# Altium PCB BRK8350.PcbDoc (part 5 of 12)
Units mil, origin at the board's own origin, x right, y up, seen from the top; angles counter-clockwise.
Board outline 9448.82 x 5905.51 mil, 8 copper layers (L1-TOP, L2-GND, L3-SIG, L4-GND, L5-PWR, L6-PWR, L7-GND, L8-BOT), stack 57.69 mil thick; 288 components, 543 nets, 1891 pads, 2032 vias.
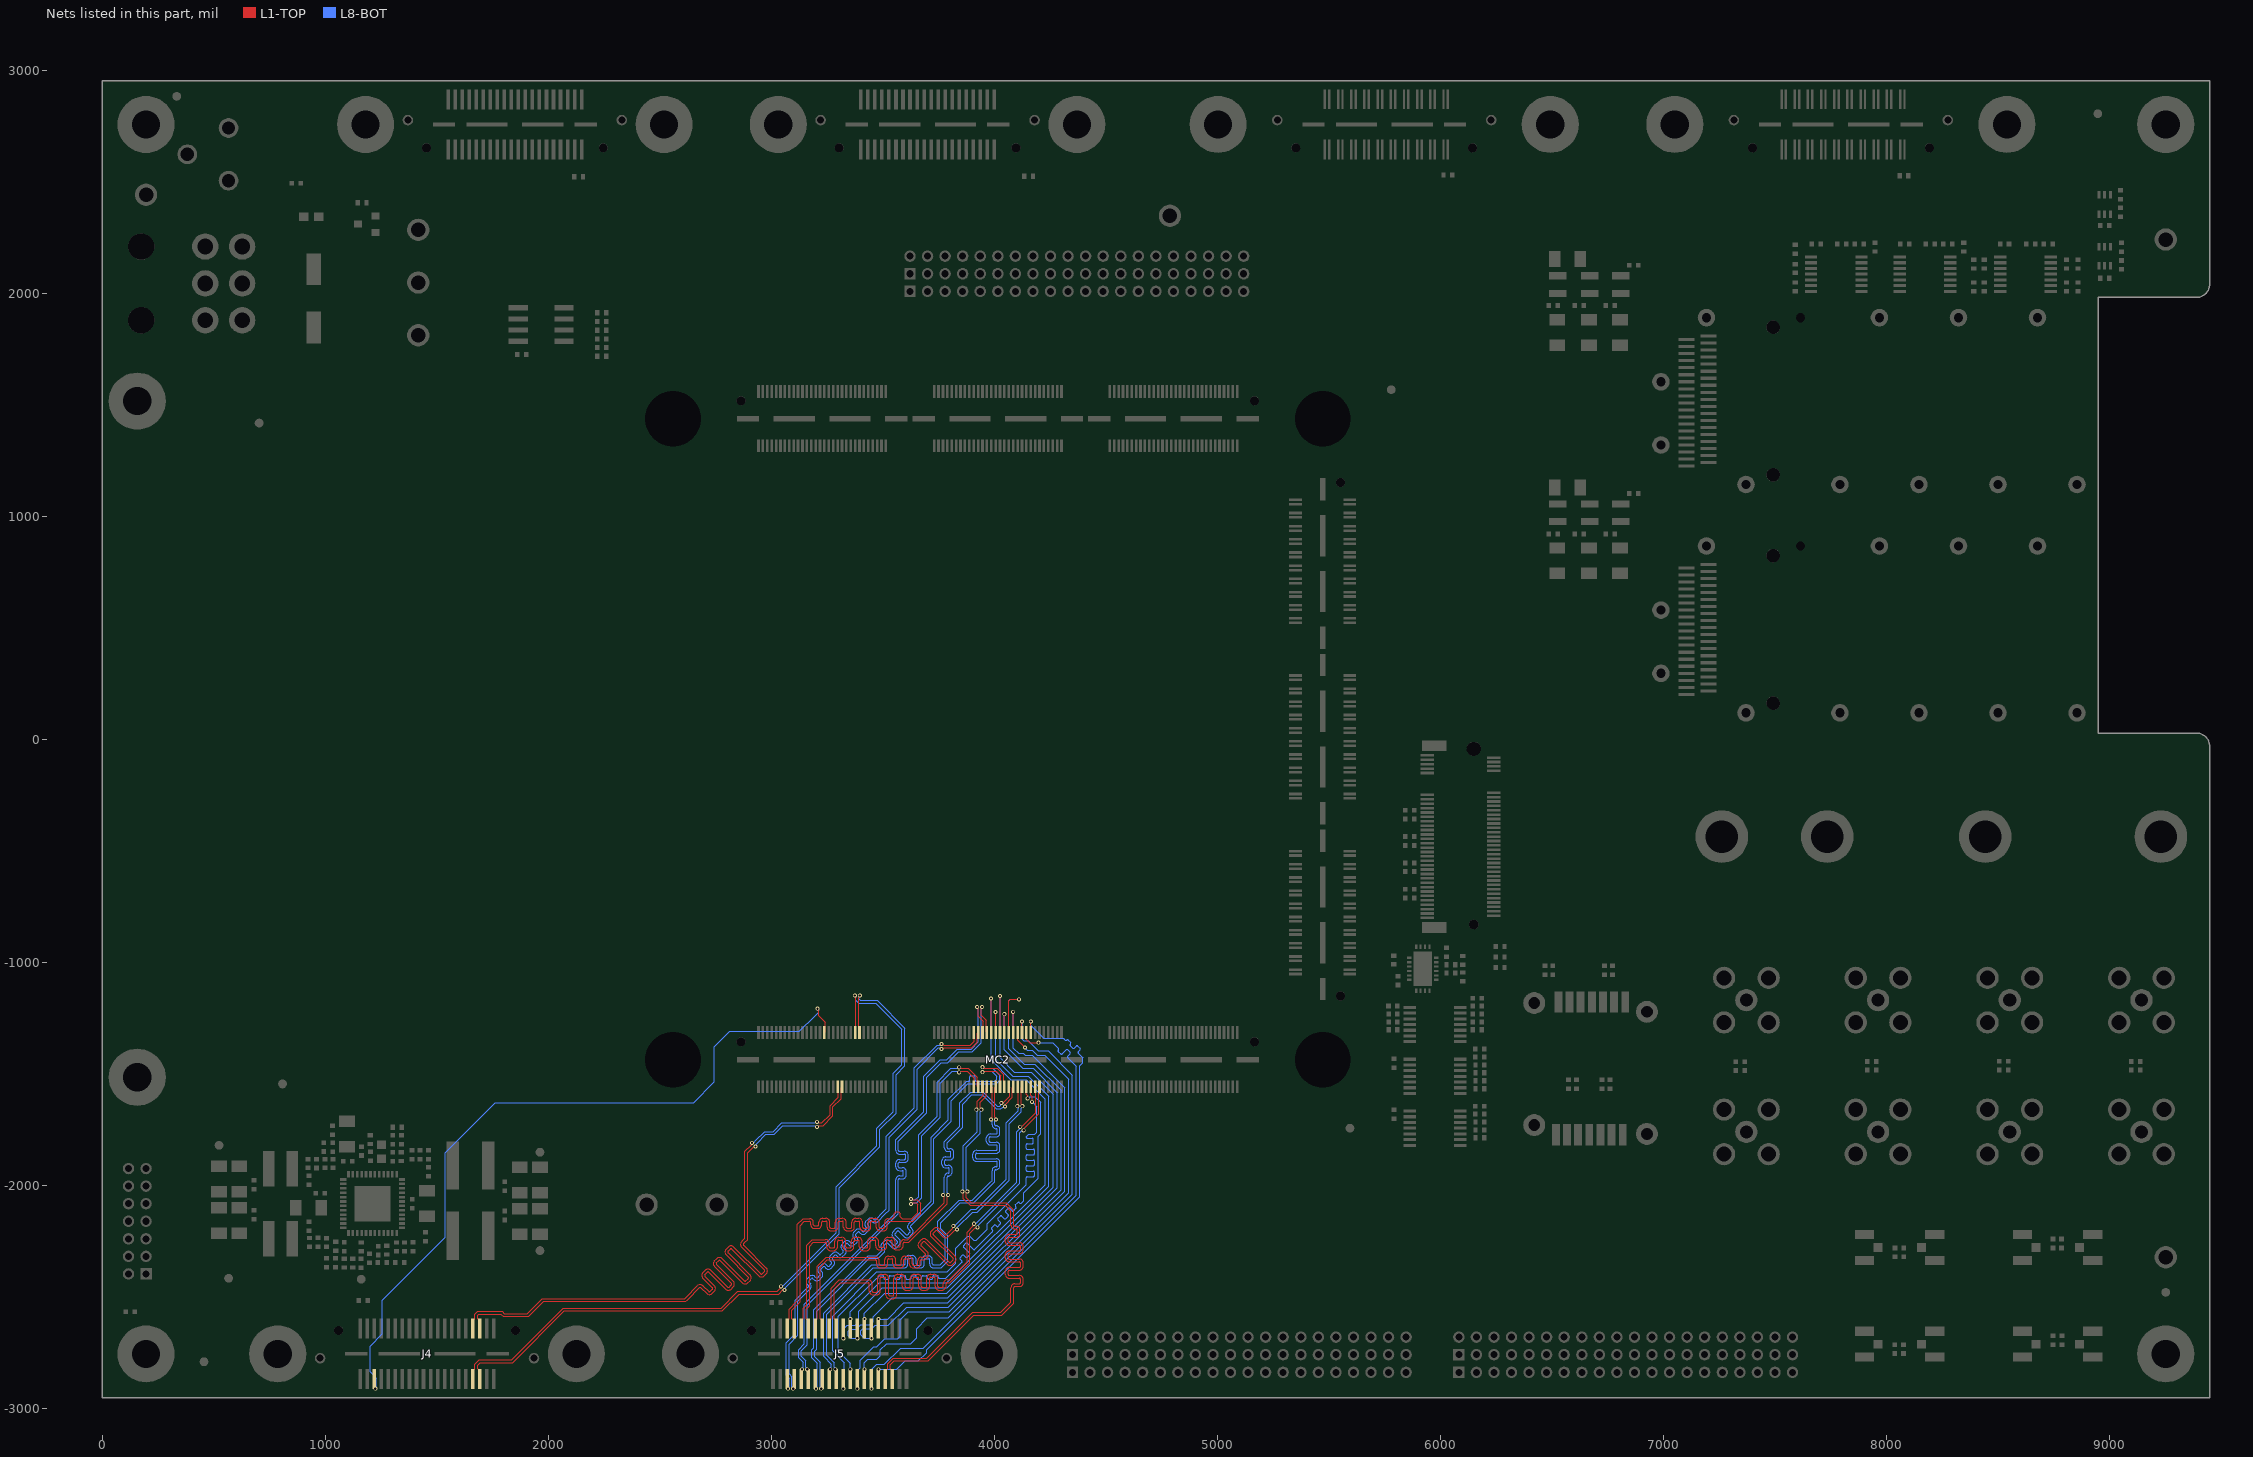
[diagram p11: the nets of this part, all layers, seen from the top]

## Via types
v1: diameter 18, hole 10, L1-TOP to L8-BOT, tented both sides, 2032 vias

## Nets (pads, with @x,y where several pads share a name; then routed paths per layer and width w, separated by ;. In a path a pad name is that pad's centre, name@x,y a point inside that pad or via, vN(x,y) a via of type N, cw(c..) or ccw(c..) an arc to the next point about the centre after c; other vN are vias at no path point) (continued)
PORTA_P2C_CLKN: J5.35 MC2.86 | length 2319.9
  L1-TOP w4.2: J5.35@3543.34,-2868.71 3543.34,-2831.96 3537.44,-2826.06 3536.35,-2826.06 3533.89,-2823.6 3533.89,-2804.85 3551.34,-2787.4 3702.86,-2787.4 3907.58,-2582.68 4033.57,-2582.68 4087.4,-2528.84 4087.4,-2503.94 4087.4,-2458.74 cw(c4092.24,-2458.74) 4092.24,-2453.9 4112.69,-2453.9 ccw(c4112.69,-2436.46) 4130.13,-2436.46 4130.13,-2421.94 ccw(c4112.69,-2421.94) 4112.69,-2404.5 4067.24,-2404.5 cw(c4067.24,-2399.66) 4062.4,-2399.66 4062.4,-2385.14 cw(c4067.24,-2385.14) 4067.24,-2380.3 4112.69,-2380.3 ccw(c4112.69,-2362.86) 4130.13,-2362.86 4130.13,-2348.34 ccw(c4112.69,-2348.34) 4112.69,-2330.9 4067.24,-2330.9 cw(c4067.24,-2326.06) 4062.4,-2326.06 4062.4,-2311.54 cw(c4067.24,-2311.54) 4067.24,-2306.7 4112.69,-2306.7 ccw(c4112.69,-2289.26) 4130.13,-2289.26 4130.13,-2274.74 ccw(c4112.69,-2274.74) 4112.69,-2257.3 4067.24,-2257.3 cw(c4067.24,-2252.46) 4062.4,-2252.46 4062.4,-2237.94 cw(c4067.24,-2237.94) 4067.24,-2233.1 4097.43,-2233.1 ccw(c4097.43,-2215.66) 4114.87,-2215.66 4114.87,-2201.14 ccw(c4097.43,-2201.14) 4097.43,-2183.7 4092.24,-2183.7 cw(c4092.24,-2178.86) 4087.4,-2178.86 4087.4,-2125.98 4087.4,-2111.03 4054.33,-2077.95 3896.85,-2077.95 3874.02,-2055.12 3874.02,-2030.02 3876.48,-2027.56 v1(3878.97,-2027.56) ; v1(3941.96,-1661.42) 3941.96,-1658.49 3937.01,-1653.54 3937.01,-1628.06 3963.01,-1602.05 3963.01,-1562.19 MC2.86@3966.55,-1558.65
  L8-BOT w4.2: v1(3878.97,-2027.56) 3878.97,-2023.82 3874.02,-2018.87 3874.02,-1828.84 3937.01,-1765.85 3937.01,-1670.1 3941.96,-1665.15 v1(3941.96,-1661.42)
PORTA_P2C_CLKP: J5.33 MC2.84 | length 2319.9
  L1-TOP w4.2: J5.33@3511.84,-2868.71 3511.84,-2831.96 3517.74,-2826.06 3518.83,-2826.06 3521.29,-2823.6 3521.29,-2799.63 3546.12,-2774.8 3697.64,-2774.8 3902.36,-2570.08 4028.35,-2570.08 4074.8,-2523.62 4074.8,-2503.94 4074.8,-2458.74 cw(c4092.24,-2458.74) 4092.24,-2441.3 4112.69,-2441.3 ccw(c4112.69,-2436.46) 4117.53,-2436.46 4117.53,-2421.94 ccw(c4112.69,-2421.94) 4112.69,-2417.1 4067.24,-2417.1 cw(c4067.24,-2399.66) 4049.8,-2399.66 4049.8,-2385.14 cw(c4067.24,-2385.14) 4067.24,-2367.7 4112.69,-2367.7 ccw(c4112.69,-2362.86) 4117.53,-2362.86 4117.53,-2348.34 ccw(c4112.69,-2348.34) 4112.69,-2343.5 4067.24,-2343.5 cw(c4067.24,-2326.06) 4049.8,-2326.06 4049.8,-2311.54 cw(c4067.24,-2311.54) 4067.24,-2294.1 4112.69,-2294.1 ccw(c4112.69,-2289.26) 4117.53,-2289.26 4117.53,-2274.74 ccw(c4112.69,-2274.74) 4112.69,-2269.9 4067.24,-2269.9 cw(c4067.24,-2252.46) 4049.8,-2252.46 4049.8,-2237.94 cw(c4067.24,-2237.94) 4067.24,-2220.5 4097.43,-2220.5 ccw(c4097.43,-2215.66) 4102.27,-2215.66 4102.27,-2201.14 ccw(c4097.43,-2201.14) 4097.43,-2196.3 4092.24,-2196.3 cw(c4092.24,-2178.86) 4074.8,-2178.86 4074.8,-2125.98 4074.8,-2116.24 4049.11,-2090.55 3891.63,-2090.55 3861.42,-2060.34 3861.42,-2030.02 3858.93,-2030.02 v1(3856.47,-2027.56) ; v1(3919.46,-1661.42) 3919.46,-1658.49 3924.41,-1653.54 3924.41,-1622.84 3950.41,-1596.84 3950.41,-1562.19 MC2.84@3946.87,-1558.65
  L8-BOT w4.2: v1(3856.47,-2027.56) 3856.47,-2023.82 3861.42,-2018.87 3861.42,-1823.62 3924.41,-1760.63 3924.41,-1670.1 3919.46,-1665.15 v1(3919.46,-1661.42)
PORTA_S0_D0P: J5.5 MC2.79 | length 2272.5
  L1-TOP w4.2: v1(3763.8,-1366.81) 3767.53,-1366.81 3772.48,-1371.76 3892.96,-1371.76 3911.04,-1353.68 3911.04,-1318.88 MC2.79@3907.5,-1315.34
  L8-BOT w4.2: v1(3075.05,-2912.07) 3075.05,-2908.34 3080.29,-2903.1 3080.29,-2864.61 3066.93,-2851.25 3066.93,-2706.59 3106.82,-2666.7 3106.82,-2515.17 3159.88,-2462.11 3165.82,-2456.17 ccw(c3162.4,-2452.75) 3165.8,-2449.3 ; 3165.79,-2449.29 3161.08,-2444.59 cw(c3173.41,-2432.25) 3161.08,-2419.92 3171.35,-2409.65 cw(c3183.68,-2421.99) 3196.01,-2409.65 3200.75,-2414.39 ccw(c3204.17,-2410.97) 3207.6,-2414.39 3217.86,-2404.13 ccw(c3214.44,-2400.7) 3217.86,-2397.28 3213.12,-2392.54 cw(c3225.46,-2380.21) 3213.12,-2367.88 3223.39,-2357.61 cw(c3235.72,-2369.94) 3248.05,-2357.61 3252.79,-2362.35 ccw(c3256.22,-2358.93) 3259.64,-2362.35 3269.91,-2352.08 ccw(c3266.48,-2348.66) 3269.91,-2345.24 3265.17,-2340.5 cw(c3277.5,-2328.17) 3265.17,-2315.84 3275.43,-2305.57 cw(c3287.77,-2317.9) 3300.1,-2305.57 3304.84,-2310.31 ccw(c3308.26,-2306.88) 3311.68,-2310.31 3321.95,-2300.04 ccw(c3318.53,-2296.62) 3321.95,-2293.19 3317.21,-2288.46 cw(c3329.54,-2276.12) 3317.21,-2263.79 3327.48,-2253.53 cw(c3339.81,-2265.86) 3352.14,-2253.53 3356.88,-2258.26 ccw(c3360.3,-2254.84) 3363.72,-2258.26 3373.99,-2248 ccw(c3370.57,-2244.57) 3373.99,-2241.15 3369.25,-2236.41 cw(c3381.58,-2224.08) 3369.25,-2211.75 3379.52,-2201.48 cw(c3391.85,-2213.81) 3404.18,-2201.48 3408.92,-2206.22 ccw(c3412.34,-2202.8) 3415.77,-2206.22 3426.03,-2195.95 ccw(c3422.61,-2192.53) 3426.03,-2189.11 3423.92,-2186.99 cw(c3436.25,-2174.66) 3423.92,-2162.33 3434.18,-2152.06 cw(c3446.52,-2164.39) 3458.85,-2152.06 3460.97,-2154.18 ccw(c3464.39,-2150.76) 3467.81,-2154.18 3502.06,-2119.93 3515.75,-2106.24 3515.75,-1779.53 3641.73,-1653.54 3641.73,-1474.1 3744.43,-1371.4 3755.47,-1371.4 3760.06,-1366.81 v1(3763.8,-1366.81)
PORTA_S1_D1P: J5.6 MC2.80 | length 2320.2
  L1-TOP w4.2: J5.6@3070.84,-2643.11 3070.84,-2606.36 3076.74,-2600.46 3077.83,-2600.46 3080.29,-2598 3080.29,-2555.26 3117.32,-2518.23 3117.32,-2175.88 3143.6,-2149.61 3148.82,-2149.61 3171.65,-2149.61 cw(c3171.65,-2167.05) 3189.09,-2167.05 3189.09,-2176.23 ccw(c3193.93,-2176.23) 3193.93,-2181.07 3208.45,-2181.07 ccw(c3208.45,-2176.23) 3213.29,-2176.23 3213.29,-2166.01 cw(c3230.73,-2166.01) 3230.73,-2148.57 3245.25,-2148.57 cw(c3245.25,-2166.01) 3262.69,-2166.01 3262.69,-2187.27 ccw(c3267.53,-2187.27) 3267.53,-2192.11 3282.05,-2192.11 ccw(c3282.05,-2187.27) 3286.89,-2187.27 3286.89,-2166.01 cw(c3304.33,-2166.01) 3304.33,-2148.57 3318.85,-2148.57 cw(c3318.85,-2166.01) 3336.29,-2166.01 3336.29,-2187.27 ccw(c3341.13,-2187.27) 3341.13,-2192.11 3355.65,-2192.11 ccw(c3355.65,-2187.27) 3360.49,-2187.27 3360.49,-2166.01 cw(c3377.93,-2166.01) 3377.93,-2148.57 3392.45,-2148.57 cw(c3392.45,-2166.01) 3409.89,-2166.01 3409.89,-2187.27 ccw(c3414.73,-2187.27) 3414.73,-2192.11 3429.25,-2192.11 ccw(c3429.25,-2187.27) 3434.09,-2187.27 3434.09,-2166.01 cw(c3451.53,-2166.01) 3451.53,-2148.57 3466.05,-2148.57 cw(c3466.05,-2166.01) 3483.49,-2166.01 3483.49,-2187.27 ccw(c3488.33,-2187.27) 3488.33,-2192.11 3502.85,-2192.11 ccw(c3502.85,-2187.27) 3507.69,-2187.27 3507.69,-2167.05 cw(c3525.13,-2167.05) 3525.13,-2149.61 3533.53,-2149.61 3543.31,-2149.61 3551.18,-2141.73 3551.18,-2127.31 3558.86,-2119.63 3571.56,-2119.63 3578.74,-2126.81 3578.74,-2141.73 3586.61,-2149.61 3630.23,-2149.61 3657.48,-2122.36 3657.48,-2086.61 3649.61,-2078.74 3633.86,-2078.74 3628.91,-2083.69 v1(3625.98,-2083.69) ; v1(3842.54,-1493.66) 3846.27,-1493.66 3851.22,-1488.71 3878.47,-1488.71 3911.04,-1521.27 3911.04,-1555.1 MC2.80@3907.5,-1558.65
  L8-BOT w4.2: v1(3625.98,-2083.69) 3629.72,-2083.69 3634.67,-2078.74 3651.68,-2078.74 3674.02,-2056.4 3674.02,-1778.74 3756.69,-1696.06 3756.69,-1542.52 3810.51,-1488.71 3833.85,-1488.71 3838.8,-1493.66 v1(3842.54,-1493.66)
PORTA_S2_D0N: J5.7 MC2.81 | length 2272.9
  L1-TOP w4.2: v1(3763.8,-1389.31) 3767.53,-1389.31 3772.48,-1384.36 3898.18,-1384.36 3923.64,-1358.9 3923.64,-1318.88 MC2.81@3927.18,-1315.34
  L8-BOT w4.2: v1(3098.12,-2912.07) 3098.12,-2908.34 3092.89,-2903.1 3092.89,-2859.39 3079.53,-2846.03 3079.53,-2711.81 3119.42,-2671.92 3119.42,-2520.39 3168.79,-2471.02 3174.73,-2465.08 ccw(c3162.4,-2452.75) 3176.57,-2442.59 3176.57,-2442.26 3174.75,-2440.44 ; 3174.73,-2440.41 3169.99,-2435.68 cw(c3173.41,-2432.25) 3169.99,-2428.83 3180.26,-2418.56 cw(c3183.68,-2421.99) 3187.1,-2418.56 3191.84,-2423.3 ccw(c3204.17,-2410.97) 3216.5,-2423.3 3226.77,-2413.04 ccw(c3214.44,-2400.7) 3226.77,-2388.37 3222.03,-2383.63 cw(c3225.46,-2380.21) 3222.03,-2376.79 3232.3,-2366.52 cw(c3235.72,-2369.94) 3239.15,-2366.52 3243.88,-2371.26 ccw(c3256.22,-2358.93) 3268.55,-2371.26 3278.81,-2360.99 ccw(c3266.48,-2348.66) 3278.82,-2336.33 3274.08,-2331.59 cw(c3277.5,-2328.17) 3274.08,-2324.75 3284.34,-2314.48 cw(c3287.77,-2317.9) 3291.19,-2314.48 3295.93,-2319.22 ccw(c3308.26,-2306.88) 3320.59,-2319.22 3330.86,-2308.95 ccw(c3318.53,-2296.62) 3330.86,-2284.29 3326.12,-2279.55 cw(c3329.54,-2276.12) 3326.12,-2272.7 3336.39,-2262.43 cw(c3339.81,-2265.86) 3343.23,-2262.43 3347.97,-2267.17 ccw(c3360.3,-2254.84) 3372.63,-2267.17 3382.9,-2256.91 ccw(c3370.57,-2244.57) 3382.9,-2232.24 3378.16,-2227.5 cw(c3381.58,-2224.08) 3378.16,-2220.66 3388.43,-2210.39 cw(c3391.85,-2213.81) 3395.27,-2210.39 3400.01,-2215.13 ccw(c3412.34,-2202.8) 3424.68,-2215.13 3434.94,-2204.86 ccw(c3422.61,-2192.53) 3434.94,-2180.2 3432.83,-2178.08 cw(c3436.25,-2174.66) 3432.83,-2171.24 3443.09,-2160.97 cw(c3446.52,-2164.39) 3449.94,-2160.97 3452.06,-2163.09 ccw(c3464.39,-2150.76) 3476.72,-2163.09 3510.96,-2128.84 3528.35,-2111.46 3528.35,-1784.75 3654.33,-1658.76 3654.33,-1479.31 3749.65,-1384 3754.75,-1384 3760.06,-1389.31 v1(3763.8,-1389.31)
PORTA_S3_D1N: J5.8 MC2.82 | length 2319.9
  L1-TOP w4.2: J5.8@3102.34,-2643.11 3102.34,-2606.36 3096.44,-2600.46 3095.35,-2600.46 3092.89,-2598 3092.89,-2560.48 3129.92,-2523.45 3129.92,-2181.1 3148.82,-2162.21 3171.65,-2162.21 cw(c3171.65,-2167.05) 3176.49,-2167.05 3176.49,-2176.23 ccw(c3193.93,-2176.23) 3193.93,-2193.67 3208.45,-2193.67 ccw(c3208.45,-2176.23) 3225.89,-2176.23 3225.89,-2166.01 cw(c3230.73,-2166.01) 3230.73,-2161.17 3245.25,-2161.17 cw(c3245.25,-2166.01) 3250.09,-2166.01 3250.09,-2187.27 ccw(c3267.53,-2187.27) 3267.53,-2204.71 3282.05,-2204.71 ccw(c3282.05,-2187.27) 3299.49,-2187.27 3299.49,-2166.01 cw(c3304.33,-2166.01) 3304.33,-2161.17 3318.85,-2161.17 cw(c3318.85,-2166.01) 3323.69,-2166.01 3323.69,-2187.27 ccw(c3341.13,-2187.27) 3341.13,-2204.71 3355.65,-2204.71 ccw(c3355.65,-2187.27) 3373.09,-2187.27 3373.09,-2166.01 cw(c3377.93,-2166.01) 3377.93,-2161.17 3392.45,-2161.17 cw(c3392.45,-2166.01) 3397.29,-2166.01 3397.29,-2187.27 ccw(c3414.73,-2187.27) 3414.73,-2204.71 3429.25,-2204.71 ccw(c3429.25,-2187.27) 3446.69,-2187.27 3446.69,-2166.01 cw(c3451.53,-2166.01) 3451.53,-2161.17 3466.05,-2161.17 cw(c3466.05,-2166.01) 3470.89,-2166.01 3470.89,-2187.27 ccw(c3488.33,-2187.27) 3488.33,-2204.71 3502.85,-2204.71 ccw(c3502.85,-2187.27) 3520.29,-2187.27 3520.29,-2167.05 cw(c3525.13,-2167.05) 3525.13,-2162.21 3533.53,-2162.21 3635.45,-2162.21 3670.08,-2127.58 3670.08,-2081.4 3654.83,-2066.14 3633.86,-2066.14 3628.91,-2061.19 v1(3625.98,-2061.19) ; v1(3842.54,-1471.16) 3846.27,-1471.16 3851.22,-1476.11 3883.69,-1476.11 3923.64,-1516.06 3923.64,-1555.1 MC2.82@3927.18,-1558.65
  L8-BOT w4.2: v1(3625.98,-2061.19) 3629.72,-2061.19 3634.67,-2066.14 3646.46,-2066.14 3661.42,-2051.18 3661.42,-1773.52 3744.09,-1690.84 3744.09,-1537.3 3805.29,-1476.11 3833.85,-1476.11 3838.8,-1471.16 v1(3842.54,-1471.16)
PORTA_S4_D2P: J5.9 MC2.83 | length 2271.4
  L1-TOP w4.2: v1(3923.39,-1200.89) 3923.39,-1204.62 3928.34,-1209.57 3928.34,-1243.31 3950.41,-1265.37 3950.41,-1311.8 MC2.83@3946.87,-1315.34
  L8-BOT w4.2: v1(3138.15,-2825.36) 3138.15,-2821.62 3142.65,-2817.12 3142.65,-2792.82 3122.63,-2772.8 3122.63,-2736.55 3148.62,-2710.56 3148.62,-2532.48 3557.55,-2123.55 3557.55,-2047.24 3557.55,-1975.73 cw(c3574.99,-1975.73) 3574.99,-1958.29 3587.66,-1958.29 ccw(c3587.66,-1953.45) 3592.5,-1953.45 3592.5,-1938.93 ccw(c3587.66,-1938.93) 3587.66,-1934.09 3574.99,-1934.09 cw(c3574.99,-1916.65) 3557.55,-1916.65 3557.55,-1902.13 cw(c3574.99,-1902.13) 3574.99,-1884.69 3597.3,-1884.69 ccw(c3597.3,-1879.85) 3602.14,-1879.85 3602.14,-1865.33 ccw(c3597.3,-1865.33) 3597.3,-1860.49 3574.99,-1860.49 cw(c3574.99,-1843.05) 3557.55,-1843.05 3557.55,-1834.65 3557.55,-1796.84 3684.25,-1670.14 3684.25,-1510.53 3757.37,-1437.41 3787.05,-1437.41 3834.69,-1389.76 3895.57,-1389.76 3928.34,-1356.99 3928.34,-1209.57 3923.39,-1204.62 v1(3923.39,-1200.89)
PORTA_S5_D3P: J5.10 MC2.96 | length 2319.9
  L1-TOP w4.2: J5.10@3133.84,-2643.11 3133.84,-2606.36 3139.74,-2600.46 3140.83,-2600.46 3143.29,-2598 3143.29,-2551.38 3159.12,-2535.54 3159.12,-2267.94 3183.76,-2243.31 3192.45,-2243.31 3242.93,-2243.31 cw(c3242.93,-2260.75) 3260.37,-2260.75 3260.37,-2275.41 ccw(c3265.21,-2275.41) 3265.21,-2280.25 3279.73,-2280.25 ccw(c3279.73,-2275.41) 3284.57,-2275.41 3284.57,-2251.31 cw(c3302.01,-2251.31) 3302.01,-2233.87 3316.53,-2233.87 cw(c3316.53,-2251.31) 3333.97,-2251.31 3333.97,-2275.41 ccw(c3338.81,-2275.41) 3338.81,-2280.25 3353.33,-2280.25 ccw(c3353.33,-2275.41) 3358.17,-2275.41 3358.17,-2251.31 cw(c3375.61,-2251.31) 3375.61,-2233.87 3390.13,-2233.87 cw(c3390.13,-2251.31) 3407.57,-2251.31 3407.57,-2275.41 ccw(c3412.41,-2275.41) 3412.41,-2280.25 3426.93,-2280.25 ccw(c3426.93,-2275.41) 3431.77,-2275.41 3431.77,-2251.31 cw(c3449.21,-2251.31) 3449.21,-2233.87 3463.73,-2233.87 cw(c3463.73,-2251.31) 3481.17,-2251.31 3481.17,-2272.35 ccw(c3486.01,-2272.35) 3486.01,-2277.19 3500.53,-2277.19 ccw(c3500.53,-2272.35) 3505.37,-2272.35 3505.37,-2251.31 cw(c3522.81,-2251.31) 3522.81,-2233.87 3537.33,-2233.87 cw(c3537.33,-2251.31) 3554.77,-2251.31 3554.77,-2271.08 ccw(c3559.61,-2271.08) 3559.61,-2275.92 3574.13,-2275.92 ccw(c3574.13,-2271.08) 3578.97,-2271.08 3578.97,-2260.75 cw(c3596.41,-2260.75) 3596.41,-2243.31 3604.81,-2243.31 3611.08,-2243.31 3775.84,-2078.55 3775.84,-2051.99 3770.89,-2047.04 v1(3770.89,-2043.31) ; v1(4031.52,-1630.97) 4032.47,-1630.01 4039.47,-1630.01 4068.52,-1600.97 4068.52,-1562.19 MC2.96@4064.98,-1558.65
  L8-BOT w4.2: v1(3770.89,-2043.31) 3770.89,-2039.57 3775.84,-2034.62 3775.84,-2015.75 3775.84,-1963.92 cw(c3793.28,-1963.92) 3793.28,-1946.48 ccw(c3793.28,-1941.64) 3798.12,-1941.64 3798.12,-1927.12 ccw(c3793.28,-1927.12) 3793.28,-1922.28 3782.14,-1922.28 cw(c3782.14,-1904.84) 3764.7,-1904.84 3764.7,-1890.32 cw(c3782.14,-1890.32) 3782.14,-1872.88 3800.93,-1872.88 ccw(c3800.93,-1868.04) 3805.77,-1868.04 3805.77,-1853.52 ccw(c3800.93,-1853.52) 3800.93,-1848.68 3793.28,-1848.68 cw(c3793.28,-1831.24) 3775.84,-1831.24 3775.84,-1822.83 3775.84,-1804.77 3845.94,-1734.66 3845.94,-1631.26 3894.71,-1582.49 3951.33,-1582.49 4014.13,-1645.29 4024.2,-1645.29 4028.88,-1640.61 4028.88,-1633.61 v1(4031.52,-1630.97)
PORTA_S6_D2N: J5.11 MC2.85 | length 2272
  L1-TOP w4.2: v1(3945.89,-1200.89) 3945.89,-1204.62 3940.94,-1209.57 3940.94,-1238.09 3963.01,-1260.15 3963.01,-1311.8 MC2.85@3966.55,-1315.34
  L8-BOT w4.2: v1(3161.22,-2825.36) 3161.22,-2821.96 3155.25,-2816 3155.25,-2787.6 3135.23,-2767.58 3135.23,-2741.77 3161.22,-2715.78 3161.22,-2537.7 3570.15,-2128.77 3570.15,-2047.24 3570.15,-1975.73 cw(c3574.99,-1975.73) 3574.99,-1970.89 3587.66,-1970.89 ccw(c3587.66,-1953.45) 3605.1,-1953.45 3605.1,-1938.93 ccw(c3587.66,-1938.93) 3587.66,-1921.49 3574.99,-1921.49 cw(c3574.99,-1916.65) 3570.15,-1916.65 3570.15,-1902.13 cw(c3574.99,-1902.13) 3574.99,-1897.29 3597.3,-1897.29 ccw(c3597.3,-1879.85) 3614.74,-1879.85 3614.74,-1865.33 ccw(c3597.3,-1865.33) 3597.3,-1847.89 3574.99,-1847.89 cw(c3574.99,-1843.05) 3570.15,-1843.05 3570.15,-1834.65 3570.15,-1802.06 3696.85,-1675.36 3696.85,-1515.75 3762.59,-1450.01 3792.27,-1450.01 3839.91,-1402.36 3900.79,-1402.36 3940.94,-1362.2 3940.94,-1209.57 3945.89,-1204.62 v1(3945.89,-1200.89)
PORTA_S7_D3N: J5.12 MC2.98 | length 2319.9
  L1-TOP w4.2: J5.12@3165.34,-2643.11 3165.34,-2606.36 3159.44,-2600.46 3158.35,-2600.46 3155.89,-2598 3155.89,-2556.59 3171.72,-2540.76 3171.72,-2273.16 3188.98,-2255.91 3192.45,-2255.91 3242.93,-2255.91 cw(c3242.93,-2260.75) 3247.77,-2260.75 3247.77,-2275.41 ccw(c3265.21,-2275.41) 3265.21,-2292.85 3279.73,-2292.85 ccw(c3279.73,-2275.41) 3297.17,-2275.41 3297.17,-2251.31 cw(c3302.01,-2251.31) 3302.01,-2246.47 3316.53,-2246.47 cw(c3316.53,-2251.31) 3321.37,-2251.31 3321.37,-2275.41 ccw(c3338.81,-2275.41) 3338.81,-2292.85 3353.33,-2292.85 ccw(c3353.33,-2275.41) 3370.77,-2275.41 3370.77,-2251.31 cw(c3375.61,-2251.31) 3375.61,-2246.47 3390.13,-2246.47 cw(c3390.13,-2251.31) 3394.97,-2251.31 3394.97,-2275.41 ccw(c3412.41,-2275.41) 3412.41,-2292.85 3426.93,-2292.85 ccw(c3426.93,-2275.41) 3444.37,-2275.41 3444.37,-2251.31 cw(c3449.21,-2251.31) 3449.21,-2246.47 3463.73,-2246.47 cw(c3463.73,-2251.31) 3468.57,-2251.31 3468.57,-2272.35 ccw(c3486.01,-2272.35) 3486.01,-2289.79 3500.53,-2289.79 ccw(c3500.53,-2272.35) 3517.97,-2272.35 3517.97,-2251.31 cw(c3522.81,-2251.31) 3522.81,-2246.47 3537.33,-2246.47 cw(c3537.33,-2251.31) 3542.17,-2251.31 3542.17,-2271.08 ccw(c3559.61,-2271.08) 3559.61,-2288.52 3574.13,-2288.52 ccw(c3574.13,-2271.08) 3591.57,-2271.08 3591.57,-2260.75 cw(c3596.41,-2260.75) 3596.41,-2255.91 3604.81,-2255.91 3616.3,-2255.91 3788.44,-2083.77 3788.44,-2051.99 3793.39,-2047.04 v1(3793.39,-2043.31) ; v1(4047.43,-1646.88) 4048.38,-1645.92 4048.38,-1638.92 4081.12,-1606.19 4081.12,-1562.19 MC2.98@4084.66,-1558.65
  L8-BOT w4.2: v1(3793.39,-2043.31) 3793.39,-2039.57 3788.44,-2034.62 3788.44,-2015.75 3788.44,-1963.92 cw(c3793.28,-1963.92) 3793.28,-1959.08 ccw(c3793.28,-1941.64) 3810.72,-1941.64 3810.72,-1927.12 ccw(c3793.28,-1927.12) 3793.28,-1909.68 3782.14,-1909.68 cw(c3782.14,-1904.84) 3777.3,-1904.84 3777.3,-1890.32 cw(c3782.14,-1890.32) 3782.14,-1885.48 3800.93,-1885.48 ccw(c3800.93,-1868.04) 3818.37,-1868.04 3818.37,-1853.52 ccw(c3800.93,-1853.52) 3800.93,-1836.08 3793.28,-1836.08 cw(c3793.28,-1831.24) 3788.44,-1831.24 3788.44,-1822.83 3788.44,-1809.99 3858.54,-1739.88 3858.54,-1636.48 3899.93,-1595.09 3946.11,-1595.09 4008.91,-1657.89 4029.42,-1657.89 4037.79,-1649.52 4044.79,-1649.52 v1(4047.43,-1646.88)
PORTA_S8_D4P: J5.13 MC2.92 | length 2272.3
  L1-TOP w4.2: v1(3946.87,-1493.14) 3947.82,-1493.14 3952.77,-1488.19 4007.89,-1488.19 4029.15,-1509.45 4029.15,-1555.1 MC2.92@4025.61,-1558.65
  L8-BOT w4.2: v1(3201.05,-2912.07) 3201.05,-2908.34 3206.29,-2903.1 3206.29,-2798.95 3181.56,-2774.22 3181.56,-2738.64 3190.52,-2729.68 3190.52,-2559.32 3434.16,-2315.68 3473.59,-2315.68 3475.4,-2313.87 3495.95,-2293.32 ccw(c3492.53,-2289.9) 3495.93,-2286.45 cw(c3508.28,-2274.14) 3495.95,-2261.81 3506.22,-2251.54 cw(c3518.55,-2263.87) 3530.88,-2251.54 3548.12,-2268.78 ccw(c3551.54,-2265.36) 3554.97,-2268.78 3565.23,-2258.52 ccw(c3561.81,-2255.09) 3565.23,-2251.67 3546.07,-2232.51 cw(c3558.4,-2220.18) 3546.07,-2207.84 3556.34,-2197.58 cw(c3568.67,-2209.91) 3581,-2197.58 3604.69,-2221.26 ccw(c3608.11,-2217.84) 3611.53,-2221.26 3621.8,-2211 ccw(c3618.38,-2207.57) 3621.8,-2204.15 3615.79,-2198.14 cw(c3628.12,-2185.81) 3615.79,-2173.48 3621.73,-2167.54 3716.54,-2072.73 3716.54,-1785.33 3794.49,-1707.38 3794.49,-1614.96 3876.38,-1533.07 3883.4,-1533.07 3885.5,-1533.07 ccw(c3885.5,-1528.23) 3890.34,-1528.23 3890.34,-1512.87 cw(c3895.18,-1512.87) 3895.18,-1508.03 3909.7,-1508.03 cw(c3909.7,-1512.87) 3914.54,-1512.87 3914.54,-1528.23 ccw(c3919.38,-1528.23) 3919.38,-1533.07 3941.36,-1533.07 4002.4,-1533.07 4011.05,-1524.41 4011.05,-1511.05 3988.19,-1488.19 3955.55,-1488.19 3950.6,-1493.14 v1(3946.87,-1493.14)
PORTA_S9_D5P: J5.14 MC2.100 | length 2320.3
  L1-TOP w4.2: J5.14@3196.84,-2643.11 3196.84,-2606.36 3202.74,-2600.46 3203.83,-2600.46 3206.29,-2598 3206.29,-2362.51 3246.75,-2322.05 3436.52,-2322.05 3467.14,-2322.05 cw(c3467.14,-2339.49) 3484.58,-2339.49 3484.58,-2352.77 ccw(c3489.42,-2352.77) 3489.42,-2357.61 3503.94,-2357.61 ccw(c3503.94,-2352.77) 3508.78,-2352.77 3508.78,-2335.16 cw(c3526.22,-2335.16) 3526.22,-2317.72 3540.74,-2317.72 cw(c3540.74,-2335.16) 3558.18,-2335.16 3558.18,-2352.77 ccw(c3563.02,-2352.77) 3563.02,-2357.61 3577.54,-2357.61 ccw(c3577.54,-2352.77) 3582.38,-2352.77 3582.38,-2335.16 cw(c3599.82,-2335.16) 3599.82,-2317.72 3614.34,-2317.72 cw(c3614.34,-2335.16) 3631.78,-2335.16 3631.78,-2352.77 ccw(c3636.62,-2352.77) 3636.62,-2357.61 3651.14,-2357.61 ccw(c3651.14,-2352.77) 3655.98,-2352.77 3655.98,-2339.49 cw(c3673.42,-2339.49) 3673.42,-2322.05 3681.82,-2322.05 3683.76,-2322.05 3684.88,-2320.92 3688.57,-2317.23 3690.82,-2314.98 ccw(c3687.4,-2311.56) 3690.8,-2308.12 ; 3690.79,-2308.1 3662.83,-2280.14 cw(c3675.16,-2267.81) 3662.83,-2255.48 3673.1,-2245.21 cw(c3685.43,-2257.55) 3697.76,-2245.21 3797.79,-2345.24 ccw(c3801.21,-2341.82) 3804.63,-2345.24 3814.9,-2334.97 ccw(c3811.48,-2331.55) 3814.9,-2328.13 3717.35,-2230.58 cw(c3729.68,-2218.25) 3717.35,-2205.92 3727.62,-2195.65 cw(c3739.95,-2207.98) 3752.28,-2195.65 3777.8,-2221.16 ccw(c3781.22,-2217.74) 3784.64,-2221.16 3808.75,-2197.05 3813.69,-2192.11 3813.69,-2185.11 v1(3816.33,-2182.47) ; v1(4102.94,-1645.67) 4102.94,-1641.93 4107.89,-1636.99 4107.89,-1562.19 MC2.100@4104.35,-1558.65
  L8-BOT w4.2: v1(3816.33,-2182.47) 3818.97,-2179.83 3825.97,-2179.83 3897.07,-2108.73 3919.05,-2108.73 4054.4,-1973.38 4054.4,-1719.62 4107.89,-1666.13 4107.89,-1654.35 4102.94,-1649.4 v1(4102.94,-1645.67)
PORTA_S10_D4N: J5.15 MC2.94 | length 2272.4
  L1-TOP w4.2: v1(3946.87,-1470.64) 3947.82,-1470.64 3952.77,-1475.59 4013.11,-1475.59 4041.75,-1504.23 4041.75,-1555.1 MC2.94@4045.29,-1558.65
  L8-BOT w4.2: v1(3224.12,-2912.07) 3224.12,-2908.34 3218.89,-2903.1 3218.89,-2793.73 3194.16,-2769 3194.16,-2743.86 3203.12,-2734.9 3203.12,-2564.54 3439.38,-2328.28 3478.81,-2328.28 3484.31,-2322.78 3504.86,-2302.23 ccw(c3492.53,-2289.9) 3506.7,-2279.74 3506.7,-2279.41 3504.88,-2277.59 cw(c3508.28,-2274.14) 3504.86,-2270.72 3515.13,-2260.45 cw(c3518.55,-2263.87) 3521.97,-2260.45 3539.21,-2277.69 ccw(c3551.54,-2265.36) 3563.87,-2277.69 3574.14,-2267.42 ccw(c3561.81,-2255.09) 3574.14,-2242.76 3554.98,-2223.6 cw(c3558.4,-2220.18) 3554.98,-2216.75 3565.25,-2206.49 cw(c3568.67,-2209.91) 3572.09,-2206.49 3595.78,-2230.17 ccw(c3608.11,-2217.84) 3620.44,-2230.17 3630.71,-2219.91 ccw(c3618.38,-2207.57) 3630.71,-2195.24 3624.7,-2189.23 cw(c3628.12,-2185.81) 3624.7,-2182.39 3630.64,-2176.45 3729.14,-2077.95 3729.14,-1790.55 3807.09,-1712.6 3807.09,-1620.18 3881.6,-1545.67 4007.62,-1545.67 4023.65,-1529.63 4023.65,-1505.83 3993.41,-1475.59 3955.55,-1475.59 3950.6,-1470.64 v1(3946.87,-1470.64)
PORTA_S11_D5N: J5.16 MC2.102 | length 2320.4
  L1-TOP w4.2: J5.16@3228.34,-2643.11 3228.34,-2606.36 3222.44,-2600.46 3221.35,-2600.46 3218.89,-2598 3218.89,-2367.73 3251.97,-2334.65 3436.52,-2334.65 3467.14,-2334.65 cw(c3467.14,-2339.49) 3471.98,-2339.49 3471.98,-2352.77 ccw(c3489.42,-2352.77) 3489.42,-2370.21 3503.94,-2370.21 ccw(c3503.94,-2352.77) 3521.38,-2352.77 3521.38,-2335.16 cw(c3526.22,-2335.16) 3526.22,-2330.32 3540.74,-2330.32 cw(c3540.74,-2335.16) 3545.58,-2335.16 3545.58,-2352.77 ccw(c3563.02,-2352.77) 3563.02,-2370.21 3577.54,-2370.21 ccw(c3577.54,-2352.77) 3594.98,-2352.77 3594.98,-2335.16 cw(c3599.82,-2335.16) 3599.82,-2330.32 3614.34,-2330.32 cw(c3614.34,-2335.16) 3619.18,-2335.16 3619.18,-2352.77 ccw(c3636.62,-2352.77) 3636.62,-2370.21 3651.14,-2370.21 ccw(c3651.14,-2352.77) 3668.58,-2352.77 3668.58,-2339.49 cw(c3673.42,-2339.49) 3673.42,-2334.65 3681.82,-2334.65 3688.98,-2334.65 3693.79,-2329.83 3699.73,-2323.89 ccw(c3687.4,-2311.56) 3701.58,-2301.4 3701.58,-2301.07 3699.75,-2299.25 ; 3699.73,-2299.23 3671.74,-2271.24 cw(c3675.16,-2267.81) 3671.74,-2264.39 3682.01,-2254.12 cw(c3685.43,-2257.55) 3688.85,-2254.12 3788.88,-2354.15 ccw(c3801.21,-2341.82) 3813.54,-2354.15 3823.81,-2343.88 ccw(c3811.48,-2331.55) 3823.81,-2319.22 3726.26,-2221.67 cw(c3729.68,-2218.25) 3726.26,-2214.83 3736.53,-2204.56 cw(c3739.95,-2207.98) 3743.37,-2204.56 3768.89,-2230.07 ccw(c3781.22,-2217.74) 3793.55,-2230.07 3817.66,-2205.96 3822.6,-2201.02 3829.6,-2201.02 v1(3832.24,-2198.38) ; MC2.102@4124.03,-1558.65 4120.49,-1562.19 4120.49,-1636.99 4125.44,-1641.93 v1(4125.44,-1645.67)
  L8-BOT w4.2: v1(3832.24,-2198.38) 3834.88,-2195.74 3834.88,-2188.74 3902.29,-2121.33 3924.27,-2121.33 4067,-1978.6 4067,-1724.84 4120.49,-1671.35 4120.49,-1654.35 4125.44,-1649.4 v1(4125.44,-1645.67)
PORTA_S12_D6P: J5.17 MC2.88 | length 2272.7
  L1-TOP w4.2: v1(3984.83,-1704.72) 3984.83,-1700.99 3989.78,-1696.04 3989.78,-1562.19 MC2.88@3986.24,-1558.65
  L8-BOT w4.2: v1(3264.15,-2825.36) 3264.15,-2821.62 3269.39,-2816.39 3269.39,-2801.74 3235.43,-2767.79 3235.43,-2573.52 3451.47,-2357.48 3586.61,-2357.48 3595.01,-2357.48 ccw(c3595.01,-2352.64) 3599.85,-2352.64 3599.85,-2332.37 cw(c3617.29,-2332.37) 3617.29,-2314.93 3631.81,-2314.93 cw(c3631.81,-2332.37) 3649.25,-2332.37 3649.25,-2352.99 ccw(c3654.09,-2352.99) 3654.09,-2357.83 3668.61,-2357.83 ccw(c3668.61,-2352.99) 3673.45,-2352.99 3673.45,-2334.45 cw(c3690.89,-2334.45) 3690.89,-2317.01 3705.41,-2317.01 cw(c3705.41,-2334.45) 3722.85,-2334.45 3722.85,-2352.64 ccw(c3727.69,-2352.64) 3727.69,-2357.48 3748.03,-2357.48 3756.69,-2357.48 3779.53,-2334.65 3779.53,-2232.28 3747.24,-2200 3747.24,-2162.21 3842.52,-2066.93 3901.74,-2066.93 3984.4,-1984.27 3989.78,-1978.89 3989.78,-1934.78 cw(c4007.22,-1934.78) 4007.22,-1917.34 4007.76,-1917.34 ccw(c4007.76,-1912.5) 4012.6,-1912.5 4012.6,-1897.98 ccw(c4007.76,-1897.98) 4007.76,-1893.14 3920.66,-1893.14 cw(c3920.66,-1875.7) 3903.22,-1875.7 3903.22,-1861.18 cw(c3920.66,-1861.18) 3920.66,-1843.74 4007.76,-1843.74 ccw(c4007.76,-1838.9) 4012.6,-1838.9 4012.6,-1824.38 ccw(c4007.76,-1824.38) 4007.76,-1819.54 3982.03,-1819.54 cw(c3982.03,-1802.1) 3964.59,-1802.1 3964.59,-1787.58 cw(c3982.03,-1787.58) 3982.03,-1770.14 4007.76,-1770.14 ccw(c4007.76,-1765.3) 4012.6,-1765.3 4012.6,-1750.78 ccw(c4007.76,-1750.78) 4007.76,-1745.94 4007.22,-1745.94 cw(c4007.22,-1728.5) 3989.78,-1728.5 3989.78,-1720.1 3989.78,-1713.41 3984.83,-1708.46 v1(3984.83,-1704.72)
PORTA_S13_D7P: J5.18 MC2.108 | length 2320.3
  L1-TOP w4.2: J5.18@3259.84,-2643.11 3259.84,-2606.36 3265.74,-2600.46 3266.83,-2600.46 3269.29,-2598 3269.29,-2460.93 3305.8,-2424.41 3306.18,-2424.41 3434.98,-2424.41 cw(c3434.98,-2441.85) 3452.42,-2441.85 3452.42,-2474.25 ccw(c3457.26,-2474.25) 3457.26,-2479.09 3471.78,-2479.09 ccw(c3471.78,-2474.25) 3476.62,-2474.25 3476.62,-2416.85 cw(c3494.06,-2416.85) 3494.06,-2399.41 3508.58,-2399.41 cw(c3508.58,-2416.85) 3526.02,-2416.85 3526.02,-2490.9 ccw(c3530.86,-2490.9) 3530.86,-2495.74 3545.38,-2495.74 ccw(c3545.38,-2490.9) 3550.22,-2490.9 3550.22,-2416.85 cw(c3567.66,-2416.85) 3567.66,-2399.41 3582.18,-2399.41 cw(c3582.18,-2416.85) 3599.62,-2416.85 3599.62,-2452.57 ccw(c3604.46,-2452.57) 3604.46,-2457.41 3618.98,-2457.41 ccw(c3618.98,-2452.57) 3623.82,-2452.57 3623.82,-2416.85 cw(c3641.26,-2416.85) 3641.26,-2399.41 3655.78,-2399.41 cw(c3655.78,-2416.85) 3673.22,-2416.85 3673.22,-2452.57 ccw(c3678.06,-2452.57) 3678.06,-2457.41 3692.58,-2457.41 ccw(c3692.58,-2452.57) 3697.42,-2452.57 3697.42,-2416.85 cw(c3714.86,-2416.85) 3714.86,-2399.41 3729.38,-2399.41 cw(c3729.38,-2416.85) 3746.82,-2416.85 3746.82,-2452.57 ccw(c3751.66,-2452.57) 3751.66,-2457.41 3766.18,-2457.41 ccw(c3766.18,-2452.57) 3771.02,-2452.57 3771.02,-2441.85 cw(c3788.46,-2441.85) 3788.46,-2424.41 3796.06,-2424.41 3796.86,-2423.61 3877.95,-2342.52 3877.95,-2210.53 3906.21,-2182.27 3906.21,-2175.27 v1(3908.85,-2172.63) ; v1(4115.94,-1737.98) 4118.58,-1735.34 4125.58,-1735.34 4186.63,-1674.29 4186.63,-1562.19 MC2.108@4183.09,-1558.65
  L8-BOT w4.2: v1(3908.85,-2172.63) 3911.49,-2169.99 3918.49,-2169.99 4101.57,-1986.91 4101.57,-1759.35 4113.3,-1747.63 4113.3,-1740.63 v1(4115.94,-1737.98)
PORTA_S14_D6N: J5.19 MC2.90 | length 2272.7
  L1-TOP w4.2: MC2.90@4005.92,-1558.65 4002.38,-1562.19 4002.38,-1696.04 4007.33,-1700.99 v1(4007.33,-1704.72)
  L8-BOT w4.2: v1(3287.22,-2825.36) 3287.22,-2821.62 3281.99,-2816.39 3281.99,-2796.52 3248.03,-2762.57 3248.03,-2578.74 3456.69,-2370.08 3586.61,-2370.08 3595.01,-2370.08 ccw(c3595.01,-2352.64) 3612.45,-2352.64 3612.45,-2332.37 cw(c3617.29,-2332.37) 3617.29,-2327.53 3631.81,-2327.53 cw(c3631.81,-2332.37) 3636.65,-2332.37 3636.65,-2352.99 ccw(c3654.09,-2352.99) 3654.09,-2370.43 3668.61,-2370.43 ccw(c3668.61,-2352.99) 3686.05,-2352.99 3686.05,-2334.45 cw(c3690.89,-2334.45) 3690.89,-2329.61 3705.41,-2329.61 cw(c3705.41,-2334.45) 3710.25,-2334.45 3710.25,-2352.64 ccw(c3727.69,-2352.64) 3727.69,-2370.08 3748.03,-2370.08 3761.91,-2370.08 3792.13,-2339.86 3792.13,-2227.06 3759.84,-2194.78 3759.84,-2167.43 3847.74,-2079.53 3906.95,-2079.53 4002.21,-1984.27 4002.38,-1984.11 4002.38,-1934.78 cw(c4007.22,-1934.78) 4007.22,-1929.94 4007.76,-1929.94 ccw(c4007.76,-1912.5) 4025.2,-1912.5 4025.2,-1897.98 ccw(c4007.76,-1897.98) 4007.76,-1880.54 3920.66,-1880.54 cw(c3920.66,-1875.7) 3915.82,-1875.7 3915.82,-1861.18 cw(c3920.66,-1861.18) 3920.66,-1856.34 4007.76,-1856.34 ccw(c4007.76,-1838.9) 4025.2,-1838.9 4025.2,-1824.38 ccw(c4007.76,-1824.38) 4007.76,-1806.94 3982.03,-1806.94 cw(c3982.03,-1802.1) 3977.19,-1802.1 3977.19,-1787.58 cw(c3982.03,-1787.58) 3982.03,-1782.74 4007.76,-1782.74 ccw(c4007.76,-1765.3) 4025.2,-1765.3 4025.2,-1750.78 ccw(c4007.76,-1750.78) 4007.76,-1733.34 4007.22,-1733.34 cw(c4007.22,-1728.5) 4002.38,-1728.5 4002.38,-1720.1 4002.38,-1713.41 4007.33,-1708.46 v1(4007.33,-1704.72)
PORTA_S15_D7N: J5.20 MC2.110 | length 2320.3
  L1-TOP w4.2: J5.20@3291.34,-2643.11 3291.34,-2606.36 3285.44,-2600.46 3284.35,-2600.46 3281.89,-2598 3281.89,-2466.15 3306.18,-2441.85 3311.02,-2437.01 3434.98,-2437.01 cw(c3434.98,-2441.85) 3439.82,-2441.85 3439.82,-2474.25 ccw(c3457.26,-2474.25) 3457.26,-2491.69 3471.78,-2491.69 ccw(c3471.78,-2474.25) 3489.22,-2474.25 3489.22,-2416.85 cw(c3494.06,-2416.85) 3494.06,-2412.01 3508.58,-2412.01 cw(c3508.58,-2416.85) 3513.42,-2416.85 3513.42,-2490.9 ccw(c3530.86,-2490.9) 3530.86,-2508.34 3545.38,-2508.34 ccw(c3545.38,-2490.9) 3562.82,-2490.9 3562.82,-2416.85 cw(c3567.66,-2416.85) 3567.66,-2412.01 3582.18,-2412.01 cw(c3582.18,-2416.85) 3587.02,-2416.85 3587.02,-2452.57 ccw(c3604.46,-2452.57) 3604.46,-2470.01 3618.98,-2470.01 ccw(c3618.98,-2452.57) 3636.42,-2452.57 3636.42,-2416.85 cw(c3641.26,-2416.85) 3641.26,-2412.01 3655.78,-2412.01 cw(c3655.78,-2416.85) 3660.62,-2416.85 3660.62,-2452.57 ccw(c3678.06,-2452.57) 3678.06,-2470.01 3692.58,-2470.01 ccw(c3692.58,-2452.57) 3710.02,-2452.57 3710.02,-2416.85 cw(c3714.86,-2416.85) 3714.86,-2412.01 3729.38,-2412.01 cw(c3729.38,-2416.85) 3734.22,-2416.85 3734.22,-2452.57 ccw(c3751.66,-2452.57) 3751.66,-2470.01 3766.18,-2470.01 ccw(c3766.18,-2452.57) 3783.62,-2452.57 3783.62,-2441.85 cw(c3788.46,-2441.85) 3788.46,-2437.01 3796.86,-2437.01 3801.28,-2437.01 3890.55,-2347.74 3890.55,-2215.75 3915.12,-2191.18 3922.12,-2191.18 v1(3924.76,-2188.54) ; v1(4131.85,-1753.89) 4134.49,-1751.25 4134.49,-1744.25 4199.23,-1679.51 4199.23,-1562.19 MC2.110@4202.77,-1558.65
  L8-BOT w4.2: v1(3924.76,-2188.54) 3927.4,-2185.9 3927.4,-2178.9 4114.17,-1992.13 4114.17,-1764.57 4122.21,-1756.54 4129.21,-1756.54 v1(4131.85,-1753.89)
PORTA_S16: J5.21 MC2.106 | length 2269.5
  L1-TOP w4.5: MC2.106@4163.4,-1558.65 4163.4,-1596.47 4169.29,-1602.36 v1(4169.29,-1625.98)
  L8-BOT w4.5: v1(3322.94,-2912.07) 3322.94,-2874.87 3327.77,-2870.03 3327.77,-2794.85 3275.59,-2742.67 3275.59,-2586.61 3473.33,-2388.88 3788.29,-2388.88 3826.77,-2350.39 3826.77,-2283.46 3880.81,-2229.42 3890.84,-2229.42 3908,-2246.58 3919.63,-2246.58 3968.5,-2197.71 3968.5,-2173.23 4142.9,-1998.83 4142.9,-1992.76 4142.9,-1966.01 cw(c4147.8,-1966.01) 4147.8,-1961.11 4175.45,-1961.11 ccw(c4175.45,-1956.21) 4180.35,-1956.21 4180.35,-1941.51 ccw(c4175.45,-1941.51) 4175.45,-1936.61 4147.77,-1936.61 cw(c4147.77,-1931.71) 4142.87,-1931.71 4142.87,-1917.01 cw(c4147.77,-1917.01) 4147.77,-1912.11 4175.45,-1912.11 ccw(c4175.45,-1907.21) 4180.35,-1907.21 4180.35,-1892.51 ccw(c4175.45,-1892.51) 4175.45,-1887.61 4147.77,-1887.61 cw(c4147.77,-1882.71) 4142.87,-1882.71 4142.87,-1868.01 cw(c4147.77,-1868.01) 4147.77,-1863.11 4175.45,-1863.11 ccw(c4175.45,-1858.21) 4180.35,-1858.21 4180.35,-1843.51 ccw(c4175.45,-1843.51) 4175.45,-1838.61 4147.77,-1838.61 cw(c4147.77,-1833.71) 4142.87,-1833.71 4142.87,-1819.01 cw(c4147.77,-1819.01) 4147.77,-1814.11 4169.73,-1814.11 ccw(c4169.73,-1809.21) 4174.63,-1809.21 4174.63,-1794.51 ccw(c4169.73,-1794.51) 4169.73,-1789.61 4147.8,-1789.61 cw(c4147.8,-1784.71) 4142.9,-1784.71 4142.9,-1783.17 4149.81,-1776.26 4154.19,-1771.88 4181.1,-1771.88 4190.86,-1762.11 4190.86,-1647.55 v1(4169.29,-1625.98)
PORTA_S17: J5.22 MC2.89 | length 2269
  L1-TOP w4.5: v1(4005.36,-1223.58) 4005.92,-1224.15 4005.92,-1240.16 MC2.89@4005.92,-1315.34
  L8-BOT w4.5: v1(3322.94,-2686.47) 3322.94,-2645.63 3340.12,-2628.44 3376.36,-2628.44 3392.28,-2612.52 3392.28,-2564.27 3497.46,-2459.1 3788.93,-2459.1 4244.09,-2003.94 4244.09,-1601.96 4152.99,-1510.86 4081.72,-1510.86 4005.36,-1434.49 4005.36,-1240.16 v1(4005.36,-1223.58)
PORTA_S18: J5.23 MC2.104 | length 2269.5
  L1-TOP w4.5: MC2.104@4143.72,-1558.65 4143.72,-1592.57 4148.86,-1597.71 4148.86,-1609.49 v1(4149.61,-1610.24)
  L8-BOT w4.5: v1(3354.44,-2825.36) 3354.44,-2797.68 3301.31,-2744.56 3301.31,-2588.45 3472.44,-2417.32 3474.69,-2417.32 ccw(c3474.69,-2412.42) 3479.59,-2412.42 3479.59,-2410.85 cw(c3484.49,-2410.85) 3484.49,-2405.95 3499.19,-2405.95 cw(c3499.19,-2410.85) 3504.09,-2410.85 3504.09,-2415.61 ccw(c3508.99,-2415.61) 3508.99,-2420.51 3523.69,-2420.51 ccw(c3523.69,-2415.61) 3528.59,-2415.61 3528.59,-2410.28 cw(c3533.49,-2410.28) 3533.49,-2405.38 3548.19,-2405.38 cw(c3548.19,-2410.28) 3553.09,-2410.28 3553.09,-2415.61 ccw(c3557.99,-2415.61) 3557.99,-2420.51 3572.69,-2420.51 ccw(c3572.69,-2415.61) 3577.59,-2415.61 3577.59,-2410.28 cw(c3582.49,-2410.28) 3582.49,-2405.38 3597.19,-2405.38 cw(c3597.19,-2410.28) 3602.09,-2410.28 3602.09,-2415.61 ccw(c3606.99,-2415.61) 3606.99,-2420.51 3621.69,-2420.51 ccw(c3621.69,-2415.61) 3626.59,-2415.61 3626.59,-2410.28 cw(c3631.49,-2410.28) 3631.49,-2405.38 3646.19,-2405.38 cw(c3646.19,-2410.28) 3651.09,-2410.28 3651.09,-2415.61 ccw(c3655.99,-2415.61) 3655.99,-2420.51 3670.69,-2420.51 ccw(c3670.69,-2415.61) 3675.59,-2415.61 3675.59,-2410.28 cw(c3680.49,-2410.28) 3680.49,-2405.38 3695.19,-2405.38 cw(c3695.19,-2410.28) 3700.09,-2410.28 3700.09,-2415.61 ccw(c3704.99,-2415.61) 3704.99,-2420.51 3719.69,-2420.51 ccw(c3719.69,-2415.61) 3724.59,-2415.61 3724.59,-2410.28 cw(c3729.49,-2410.28) 3729.49,-2405.38 3744.19,-2405.38 cw(c3744.19,-2410.28) 3749.09,-2410.28 3749.09,-2412.42 ccw(c3753.99,-2412.42) 3753.99,-2417.32 3783.18,-2417.32 3852.64,-2347.86 3854.23,-2346.27 ccw(c3850.76,-2342.81) 3854.23,-2339.34 3846.74,-2331.85 cw(c3850.2,-2328.39) 3846.74,-2324.92 3857.13,-2314.53 cw(c3860.6,-2317.99) 3864.06,-2314.53 3871.84,-2322.31 ccw(c3875.3,-2318.84) 3878.77,-2322.31 3889.16,-2311.91 ccw(c3885.7,-2308.45) 3889.16,-2304.98 3862.34,-2278.16 cw(c3865.8,-2274.7) 3862.34,-2271.23 3872.73,-2260.84 cw(c3876.2,-2264.3) 3879.66,-2260.84 3906.2,-2287.37 ccw(c3909.66,-2283.91) 3913.13,-2287.37 3934.9,-2265.6 3991.02,-2209.48 3992.61,-2207.89 ccw(c3989.14,-2204.43) 3992.61,-2200.96 3988.47,-2196.82 cw(c3991.93,-2193.36) 3988.47,-2189.89 3998.86,-2179.5 cw(c4002.33,-2182.96) 4005.79,-2179.5 4010.22,-2183.92 ccw(c4013.69,-2180.46) 4017.15,-2183.92 4027.55,-2173.53 ccw(c4024.08,-2170.06) 4027.55,-2166.6 4016.51,-2155.56 cw(c4019.97,-2152.1) 4016.51,-2148.63 4026.9,-2138.24 cw(c4030.37,-2141.71) 4033.83,-2138.24 4044.87,-2149.28 ccw(c4048.33,-2145.81) 4051.8,-2149.28 4062.19,-2138.88 ccw(c4058.73,-2135.42) 4062.19,-2131.95 4051.16,-2120.92 cw(c4054.62,-2117.45) 4051.16,-2113.99 4061.55,-2103.59 cw(c4065.02,-2107.06) 4068.48,-2103.59 4079.52,-2114.63 ccw(c4082.98,-2111.16) 4086.45,-2114.63 4096.84,-2104.23 ccw(c4093.38,-2100.77) 4096.84,-2097.3 4094.88,-2095.34 cw(c4098.34,-2091.88) 4094.88,-2088.41 4105.27,-2078.02 cw(c4108.74,-2081.48) 4112.2,-2078.02 4113.88,-2079.69 ccw(c4117.34,-2076.23) 4120.81,-2079.69 4131.75,-2068.75 4131.75,-2033.32 4196.85,-1968.22 4196.85,-1779.52 4207.36,-1769.01 4207.36,-1628.3 4181.58,-1602.53 4157.81,-1602.53 4150.1,-1610.24 v1(4149.61,-1610.24)
PORTA_S19: J5.24 MC2.87 | length 2268.4
  L1-TOP w4.5: v1(3985.45,-1162.96) 3986.3,-1163.81 3986.3,-1240.16 MC2.87@3986.3,-1315.27
  L8-BOT w4.5: v1(3354.44,-2599.76) 3354.44,-2566.82 3484.25,-2437.01 3787.4,-2437.01 4227.39,-1997.02 4227.39,-1612.6 4226.59,-1611.8 4142.35,-1527.56 4074.8,-1527.56 3985.71,-1438.47 3985.71,-1240.16 3985.71,-1163.22 v1(3985.45,-1162.96)
PORTA_S20: J5.25 MC2.99 | length 2268.8
  L1-TOP w4.5: MC2.99@4104.35,-1315.34 4104.35,-1349.35 v1(4137.81,-1382.81)
  L8-BOT w4.5: v1(3385.94,-2912.07) 3385.94,-2832.68 3399.87,-2818.74 3399.87,-2784.07 3460.31,-2723.63 3473.08,-2723.63 3507.74,-2688.98 3566.93,-2688.98 3578.74,-2677.17 3578.74,-2602.4 3614.21,-2566.93 3798.71,-2566.93 4333,-2032.64 4333,-1611.8 4333.85,-1610.95 4333.85,-1523.7 4226.69,-1416.54 4192.05,-1416.54 4170.29,-1394.78 4146.64,-1394.78 4137.81,-1385.95 v1(4137.81,-1382.81)
PORTA_S21: J5.26 MC2.93 | length 2269.7
  L1-TOP w4.5: v1(4044.82,-1233.07) 4045.42,-1233.67 4045.42,-1240.16 4045.42,-1315.21 MC2.93@4045.29,-1315.34
  L8-BOT w4.5: v1(3385.94,-2686.47) 3355.76,-2686.47 3344.58,-2675.29 3344.58,-2655.48 3354.44,-2645.63 3381.93,-2645.63 3401.66,-2625.89 3442.45,-2625.89 3456.88,-2611.47 3456.88,-2590.37 3543.31,-2503.94 3791.05,-2503.94 4282.71,-2012.28 4282.71,-1585.44 4173.54,-1476.26 4128.09,-1476.26 4045.29,-1393.47 4045.29,-1240.16 4045.29,-1233.54 v1(4044.82,-1233.07)
PORTA_S22: J5.27 MC2.101 | length 2269.5
  L1-TOP w4.5: MC2.101@4124.03,-1315.34 4124.03,-1265.84 v1(4124.13,-1265.74)
  L8-BOT w4.5: v1(3417.44,-2825.36) 3417.44,-2795.16 3431.59,-2781.01 3472.73,-2781.01 3488.62,-2765.12 3488.62,-2738.08 3516.96,-2709.75 3625.14,-2709.75 3651.78,-2683.1 3651.78,-2642.68 3699.98,-2594.49 3794.49,-2594.49 4349.5,-2039.48 4349.5,-1506.03 4241.4,-1397.93 4197.9,-1397.93 4152.98,-1353.01 4131.81,-1353.01 4124.23,-1345.43 v1@4124.23,-1265.64
PORTA_S23: J5.28 MC2.91 | length 2268.3
  L1-TOP w4.5: v1(4025.4,-1151.78) 4025.67,-1152.05 MC2.91@4025.67,-1315.27
  L8-BOT w4.5: v1(3417.44,-2599.76) 3417.44,-2574.69 3507.87,-2484.25 3787.4,-2484.25 4263.78,-2007.87 4263.78,-1611.8 4263.78,-1592.72 4164.97,-1493.92 4090.51,-1493.92 4025.77,-1429.17 4025.77,-1152.14 v1(4025.4,-1151.78)
PORTA_S24: J5.29 MC2.103 | length 2269.5
  L1-TOP w4.5: MC2.103@4143.72,-1315.34 4143.72,-1346.13 4158.69,-1361.1 v1(4197.92,-1361.1)
  L8-BOT w4.5: v1(3448.94,-2912.07) 3448.94,-2826.65 3472.44,-2803.15 3507.45,-2803.15 3580.49,-2730.11 3682.2,-2730.11 4366.9,-2045.41 4366.9,-1465.61 4348.21,-1446.92 4346.62,-1445.33 4329.29,-1428 cw(c4332.76,-1424.54) 4329.29,-1421.07 4340.04,-1410.33 ccw(c4336.58,-1406.86) 4340.04,-1403.4 4329.65,-1393 ccw(c4326.18,-1396.47) 4322.72,-1393 4304.24,-1411.48 cw(c4300.78,-1408.01) 4297.31,-1411.48 4286.92,-1401.08 cw(c4290.38,-1397.62) 4286.92,-1394.15 4287.71,-1393.36 ccw(c4284.25,-1389.89) 4287.71,-1386.43 4266.4,-1365.11 4264.81,-1363.52 4262.39,-1361.1 v1(4197.92,-1361.1)
PORTA_S25: J5.30 MC2.97 | length 2269.3
  L1-TOP w4.5: v1(4084.5,-1222.58) 4084.81,-1222.89 4084.81,-1240.16 4084.81,-1315.19 MC2.97@4084.66,-1315.34
  L8-BOT w4.5: v1(3448.94,-2686.47) 3417.86,-2686.47 3400.81,-2669.42 3400.81,-2652.65 3410.15,-2643.31 3450.94,-2643.31 3465.43,-2628.82 3524.72,-2628.82 3606.45,-2547.09 3794.56,-2547.09 4315.71,-2025.94 4315.71,-1563.74 4169.29,-1417.32 4138.07,-1417.32 4129.8,-1409.06 4108.57,-1409.06 4085.22,-1385.72 4085.22,-1288.79 4084.95,-1288.52 4084.95,-1240.16 4084.95,-1223.04 v1(4084.5,-1222.58)
PORTA_S26: J5.31 MC2.105 | length 2269.4
  L1-TOP w4.5: MC2.105@4163.5,-1315.24 4163.5,-1265.74 v1(4163.6,-1265.64)
  L8-BOT w4.5: v1(3480.44,-2825.36) 3562.73,-2825.36 3600.68,-2787.4 3660.1,-2787.4 3697.42,-2750.08 3697.42,-2738.51 4383.61,-2052.33 4383.61,-1464.71 4397.64,-1450.67 4397.64,-1429.13 4395.51,-1427 4393.92,-1425.41 4376.59,-1408.09 cw(c4380.06,-1404.62) 4376.59,-1401.16 4384.52,-1393.23 ccw(c4381.06,-1389.77) 4384.52,-1386.3 4374.13,-1375.91 ccw(c4370.66,-1379.37) 4367.2,-1375.91 4358.04,-1385.06 cw(c4354.57,-1381.6) 4351.11,-1385.06 4340.71,-1374.67 cw(c4344.18,-1371.2) 4340.71,-1367.74 4341.94,-1366.51 ccw(c4338.48,-1363.04) 4341.94,-1359.58 4331.55,-1349.19 ccw(c4328.09,-1352.65) 4324.62,-1349.19 cw(c4321.15,-1345.72) 4317.69,-1349.19 4311.94,-1343.44 4310.35,-1341.85 ; v1(4163.6,-1265.64) 4163.6,-1283.64 4221.78,-1341.82 4310.33,-1341.82
PORTA_S27: J5.32 MC2.95 | length 2269.1
  L1-TOP w4.5: MC2.95@4065.04,-1315.27 4065.04,-1240.16 4065.04,-1172.94 4071.18,-1166.8 4110.26,-1166.8 v1(4110.57,-1166.49)
  L8-BOT w4.5: v1(3480.44,-2599.76) 3522.29,-2599.76 3594.49,-2527.56 3790.76,-2527.56 4299.21,-2019.11 4299.21,-1574.64 4181.77,-1457.2 4134.36,-1457.2 4064.93,-1387.77 4064.93,-1240.16 4064.93,-1172.89 4071.03,-1166.8 4110.26,-1166.8 v1(4110.57,-1166.49)
PORTB_C2P_CLKN: J4.36 MC2.40 | length 3427.4
  L1-TOP w4.2: J4.36@1692.94,-2643.11 1692.94,-2606.36 1687.04,-2600.46 1685.95,-2600.46 1683.49,-2598 1683.49,-2583.05 1688.71,-2577.84 1787.91,-2577.84 1798.04,-2587.97 1912.03,-2587.97 1979.39,-2520.61 2617.31,-2520.61 2623.17,-2514.74 2627.27,-2510.64 2678.05,-2459.87 cw(c2681.47,-2463.29) 2684.91,-2459.89 2710.14,-2485.12 ccw(c2722.47,-2472.79) 2734.8,-2485.12 2745.07,-2474.85 ccw(c2732.74,-2462.52) 2745.07,-2450.19 2702.14,-2407.26 cw(c2705.57,-2403.84) 2702.14,-2400.41 2712.41,-2390.15 cw(c2715.83,-2393.57) 2719.26,-2390.15 2794.96,-2465.85 ccw(c2807.29,-2453.52) 2819.62,-2465.85 2829.89,-2455.59 ccw(c2817.56,-2443.25) 2829.89,-2430.92 2754.19,-2355.22 cw(c2757.61,-2351.79) 2754.19,-2348.37 2764.45,-2338.1 cw(c2767.88,-2341.53) 2771.3,-2338.1 2870.65,-2437.46 ccw(c2882.98,-2425.12) 2895.31,-2437.46 2905.58,-2427.19 ccw(c2893.25,-2414.86) 2905.58,-2402.52 2806.23,-2303.17 cw(c2809.65,-2299.75) 2806.23,-2296.33 2816.5,-2286.06 cw(c2819.92,-2289.48) 2823.34,-2286.06 2943.28,-2406 ccw(c2955.61,-2393.67) 2967.94,-2406 2978.21,-2395.73 ccw(c2965.88,-2383.4) 2978.21,-2371.07 2875.95,-2268.81 cw(c2879.37,-2265.39) 2875.95,-2261.96 2881.89,-2256.02 2894.49,-2243.42 2894.49,-1853.54 2921.26,-1826.77 2928.26,-1826.77 v1(2929.22,-1825.82) ; v1(3204.72,-1738.02) 3208.46,-1738.02 3213.41,-1733.07 3232.08,-1733.07 3276.14,-1689.01 3276.14,-1648.71 3313.4,-1611.45 3313.4,-1562.19 MC2.40@3316.94,-1558.65
  L8-BOT w4.2: v1(2929.22,-1825.82) 2931.86,-1823.18 2931.86,-1816.18 2936.53,-1811.5 2975.65,-1772.38 3013.28,-1772.38 3052.58,-1733.07 3196.04,-1733.07 3200.99,-1738.02 v1(3204.72,-1738.02)
PORTB_C2P_CLKP: J4.34 MC2.38 | length 3427.5
  L1-TOP w4.2: J4.34@1661.44,-2643.11 1661.44,-2606.36 1667.34,-2600.46 1668.43,-2600.46 1670.89,-2598 1670.89,-2577.84 1683.49,-2565.24 1793.13,-2565.24 1803.26,-2575.37 1906.81,-2575.37 1974.17,-2508.01 2612.09,-2508.01 2614.27,-2505.83 2618.36,-2501.73 2669.14,-2450.96 cw(c2681.47,-2463.29) 2691.62,-2449.11 2691.95,-2449.11 2693.78,-2450.94 ; 2693.23,-2391.5 2703.5,-2381.24 cw(c2715.83,-2393.57) 2728.16,-2381.24 2803.87,-2456.94 ccw(c2807.29,-2453.52) 2810.71,-2456.94 2820.98,-2446.68 ccw(c2817.56,-2443.25) 2820.98,-2439.83 2745.28,-2364.13 cw(c2757.61,-2351.79) 2745.28,-2339.46 2755.54,-2329.19 cw(c2767.88,-2341.53) 2780.21,-2329.19 2879.56,-2428.55 ccw(c2882.98,-2425.12) 2886.4,-2428.55 2896.67,-2418.28 ccw(c2893.25,-2414.86) 2896.67,-2411.43 2797.32,-2312.08 cw(c2809.65,-2299.75) 2797.32,-2287.42 2807.59,-2277.15 cw(c2819.92,-2289.48) 2832.25,-2277.15 2952.19,-2397.09 ccw(c2955.61,-2393.67) 2959.04,-2397.09 2969.3,-2386.82 ccw(c2965.88,-2383.4) 2969.3,-2379.98 2867.04,-2277.72 cw(c2879.37,-2265.39) 2867.04,-2253.05 2872.98,-2247.11 2881.89,-2238.2 2881.89,-1848.32 2912.35,-1817.86 2912.35,-1810.86 v1(2913.31,-1809.91) ; 2693.23,-2391.5 ccw(c2705.57,-2403.84) 2693.23,-2416.17 2736.16,-2459.1 cw(c2732.74,-2462.52) 2736.16,-2465.94 2725.9,-2476.21 cw(c2722.47,-2472.79) 2719.05,-2476.21 2693.8,-2450.96 ; v1(3204.72,-1715.52) 3208.46,-1715.52 3213.41,-1720.47 3226.86,-1720.47 3263.54,-1683.79 3263.54,-1643.49 3300.8,-1606.23 3300.8,-1562.19 MC2.38@3297.26,-1558.65
  L8-BOT w4.2: v1(2913.31,-1809.91) 2915.95,-1807.27 2922.95,-1807.27 2931.31,-1798.9 2970.44,-1759.78 3008.06,-1759.78 3047.36,-1720.47 3196.04,-1720.47 3200.99,-1715.52 v1(3204.72,-1715.52)
PORTB_P2C_CLKN: J4.35 MC2.47 | length 3427.5
  L1-TOP w4.2: J4.35@1692.94,-2868.71 1692.94,-2831.96 1687.04,-2826.06 1685.95,-2826.06 1683.49,-2823.6 1683.49,-2807.09 1695.3,-2795.28 1840.65,-2795.28 2072.27,-2563.66 2780.93,-2563.66 2855.61,-2488.98 3032.78,-2488.98 3054.41,-2467.34 3057.89,-2467.34 v1(3059.65,-2469.1) ; MC2.47@3395.69,-1315.34 3392.14,-1311.8 3392.14,-1158.29 3397.09,-1153.34 v1(3397.09,-1149.61)
  L8-BOT w4.2: v1(3059.65,-2469.1) 3062.29,-2466.46 3062.29,-2459.46 3303.94,-2217.82 3303.94,-2011.02 3486.55,-1828.41 3486.55,-1749.61 3559.84,-1676.32 3559.84,-1503.94 3598.43,-1465.36 3598.43,-1295.28 3474.06,-1170.91 3398.48,-1170.91 3392.14,-1164.57 3392.14,-1158.29 3397.09,-1153.34 v1(3397.09,-1149.61)
PORTB_P2C_CLKP: J4.33 MC2.45 | length 3427.5
  L1-TOP w4.2: J4.33@1661.44,-2868.71 1661.44,-2831.96 1667.34,-2826.06 1668.43,-2826.06 1670.89,-2823.6 1670.89,-2801.87 1690.08,-2782.68 1835.43,-2782.68 2067.05,-2551.06 2079.65,-2551.06 2775.71,-2551.06 2850.39,-2476.38 3027.56,-2476.38 3045.5,-2458.43 3043.74,-2456.67 v1(3043.74,-2453.19) ; v1(3374.59,-1149.61) 3374.59,-1153.34 3379.54,-1158.29 3379.54,-1311.8 MC2.45@3376,-1315.34
  L8-BOT w4.2: v1(3043.74,-2453.19) 3046.38,-2450.55 3053.39,-2450.55 3291.34,-2212.6 3291.34,-2005.8 3473.95,-1823.19 3473.95,-1744.39 3547.24,-1671.1 3547.24,-1498.72 3585.83,-1460.14 3585.83,-1300.49 3468.84,-1183.51 3393.26,-1183.51 3379.54,-1169.79 3379.54,-1158.29 3374.59,-1153.34 v1(3374.59,-1149.61)
PORTB_S0_D0P: J4.5 MC2.31 | length 3378.8
  L1-TOP w4.2: v1(3206.86,-1208.57) 3207.79,-1208.57 3211.81,-1212.6 3211.81,-1239.37 3241.75,-1269.31 3241.75,-1311.8 MC2.31@3238.2,-1315.34
  L8-BOT w4.2: v1(1224.66,-2912.07) 1224.66,-2908.34 1229.89,-2903.1 1229.89,-2864.61 1202.04,-2836.76 1202.04,-2721.08 1256.43,-2666.7 1256.43,-2515.17 1538.58,-2233.01 1538.58,-1853.97 1762.63,-1629.92 2651.41,-1629.92 2744.81,-1536.52 2744.81,-1454.33 2744.81,-1379.1 2813.68,-1310.23 2905.51,-1310.23 3126.44,-1310.23 3196.52,-1240.16 3211.81,-1224.86 3211.81,-1217.26 3206.86,-1212.31 v1(3206.86,-1208.57)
